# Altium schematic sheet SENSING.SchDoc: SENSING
size A3; DocumentNumber: 6; SheetNumber: 6; SheetTotal: 6
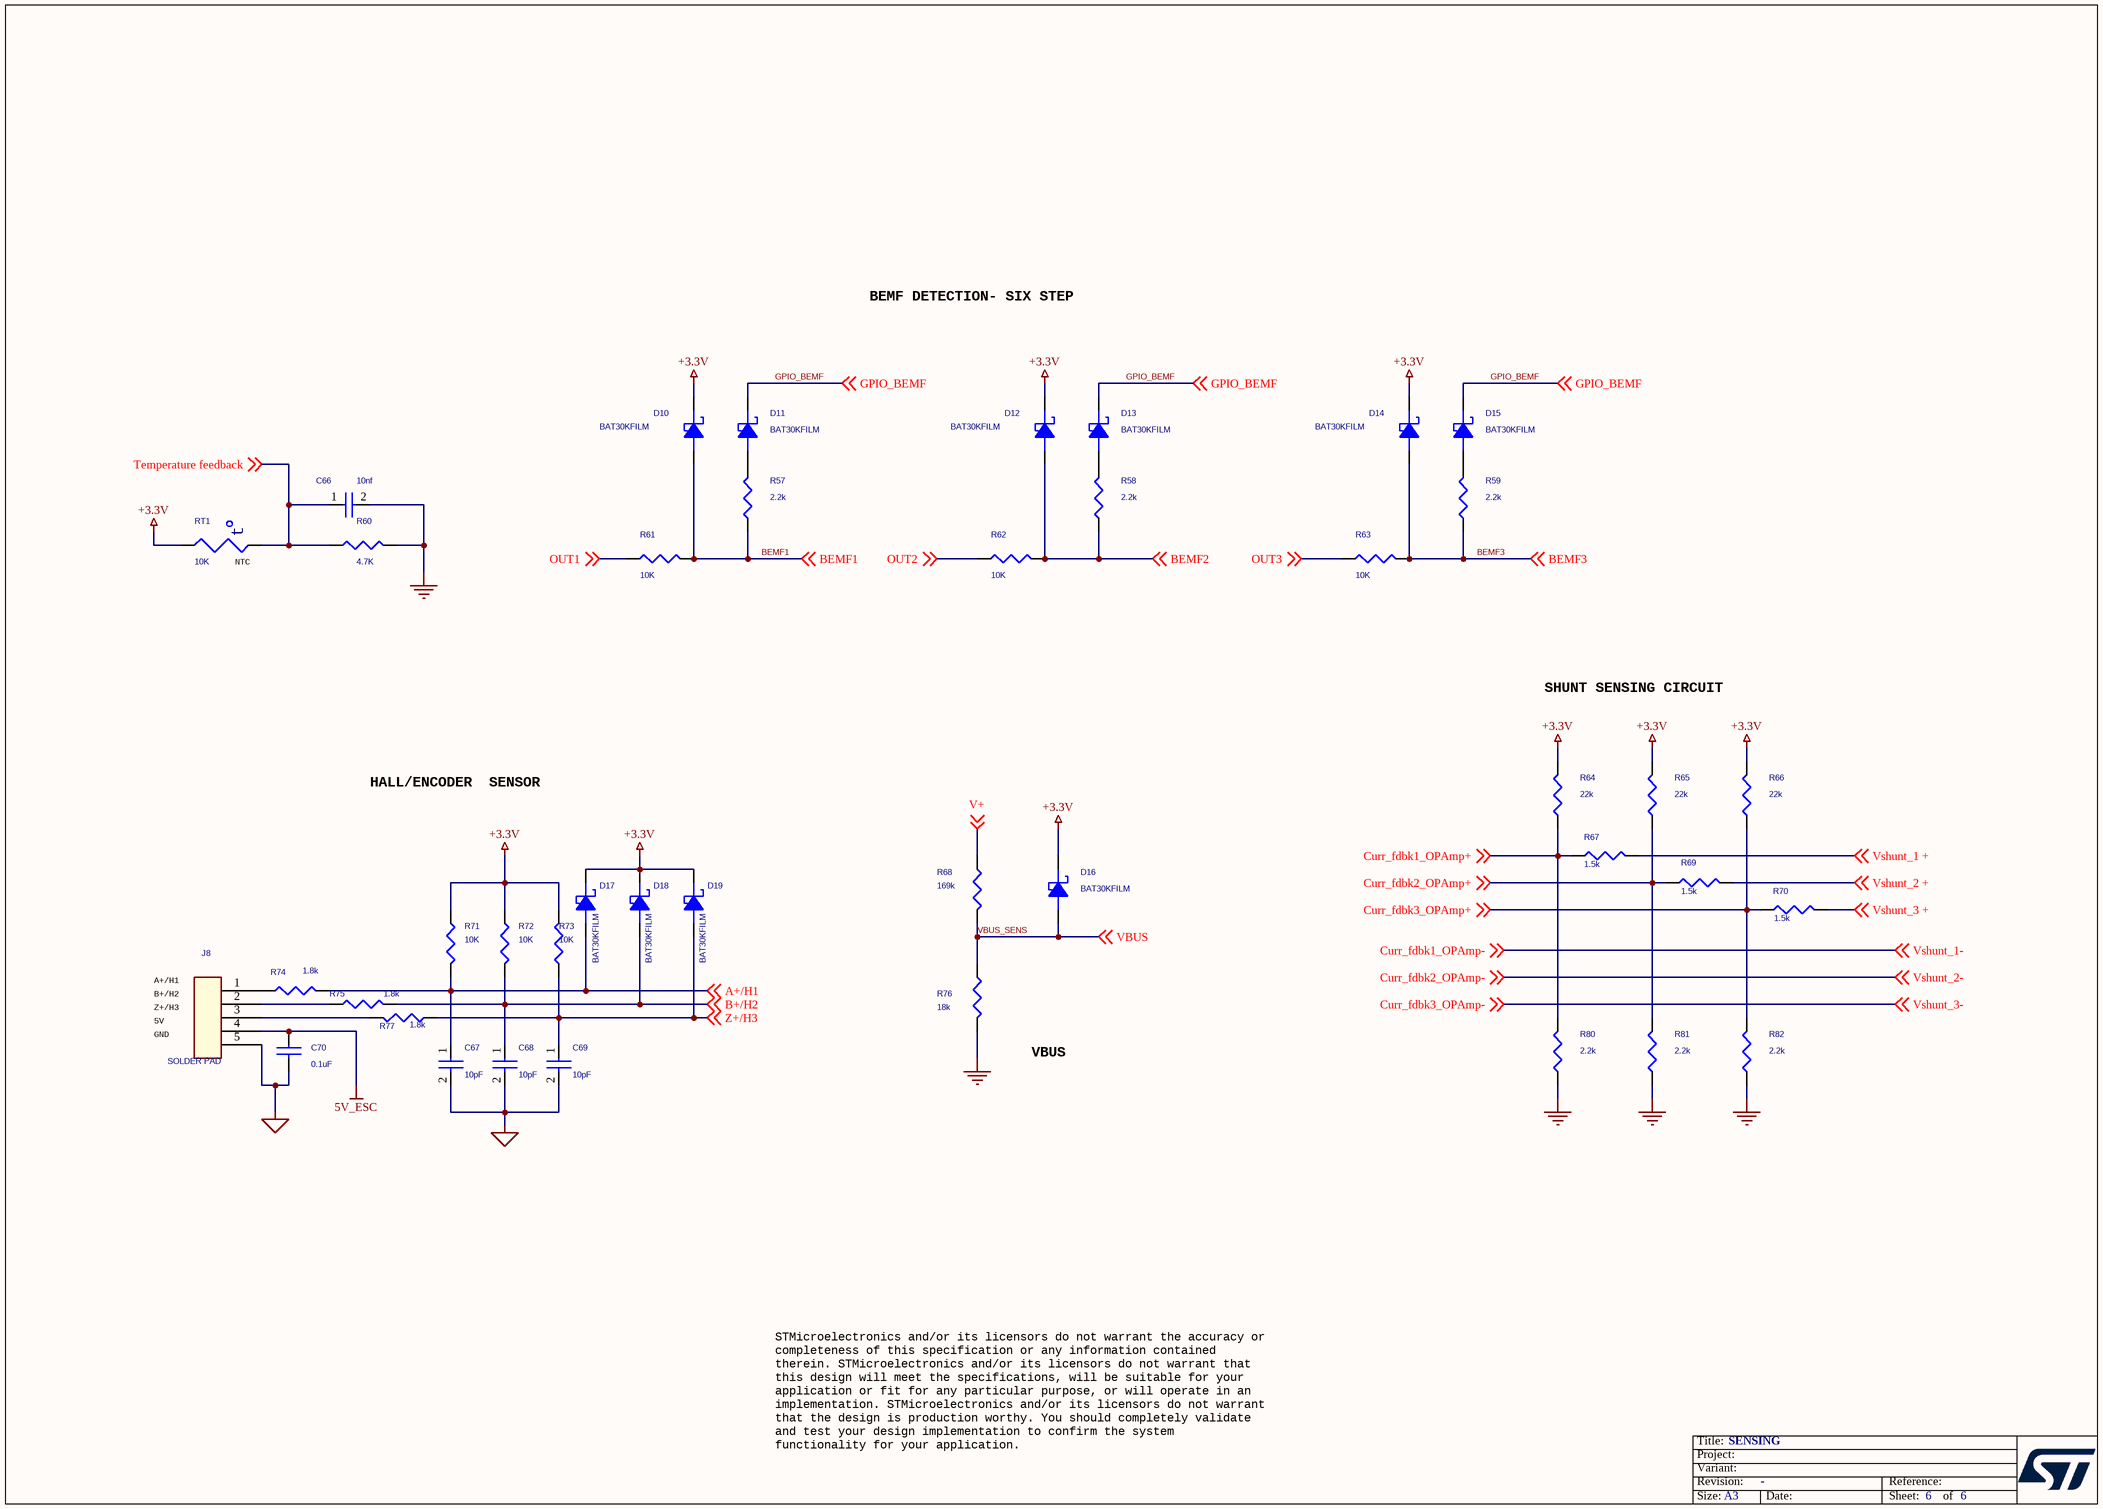
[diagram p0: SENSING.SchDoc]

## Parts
C66  10nf  [C_0402]
C67  10pF  [C_0402]
C68  10pF  [C_0402]
C69  10pF  [C_0402]
C70  0.1uF  [C_0402]
D10  BAT30KFILM  [sodfl160x80x65l30x30n]
D11  BAT30KFILM  [sodfl160x80x65l30x30n]
D12  BAT30KFILM  [sodfl160x80x65l30x30n]
D13  BAT30KFILM  [sodfl160x80x65l30x30n]
D14  BAT30KFILM  [sodfl160x80x65l30x30n]
D15  BAT30KFILM  [sodfl160x80x65l30x30n]
D16  BAT30KFILM  [sodfl160x80x65l30x30n]
D17  BAT30KFILM  [sodfl160x80x65l30x30n]
D18  BAT30KFILM  [sodfl160x80x65l30x30n]
D19  BAT30KFILM  [sodfl160x80x65l30x30n]
J8  SOLDER PAD  [SOLDER_PAD_5PIN_SMD]
R57  2.2k  [R_0402]
R58  2.2k  [R_0402]
R59  2.2k  [R_0402]
R60  4.7K  [R_0402]
R61  10K  [R_0603_HD]
R62  10K  [R_0603_HD]
R63  10K  [R_0603]
R64  22k  [r_0402]
R65  22k  [r_0402]
R66  22k  [r_0402]
R67  1.5k  [R_0402]
R68  169k  [R_0402]
R69  1.5k  [R_0402]
R70  1.5k  [R_0402]
R71  10K  [R_0402]
R72  10K  [R_0402]
R73  10K  [R_0402]
R74  1.8k  [R_0402]
R75  1.8k  [R_0402]
R76  18k  [R_0402]
R77  1.8k  [R_0402]
R80  2.2k  [R_0402]
R81  2.2k  [R_0402]
R82  2.2k  [R_0402]
RT1  10K  [R_0402]

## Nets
5V_ESC: C70.1 J8.4
+3.3V: D10.C D12.C D14.C D16.C D17.C D18.C D19.C R64.2 R65.2 R66.2 R71.1 R72.1 R73.2 RT1.1
GND: C66.2 R60.2 R76.2 R80.1 R81.1 R82.1
GND_SIGNAL: C67.2 C68.2 C69.2 C70.2 J8.5
A+/H1: C67.1 D17.A R71.2 R74.2 ; off-sheet A+/H1
B+/H2: C68.1 D18.A R72.2 R75.2 ; off-sheet B+/H2
BEMF1: D10.A R57.1 R61.2 ; off-sheet BEMF1
BEMF2: D12.A R58.1 R62.2 ; off-sheet BEMF2
BEMF3: D14.A R59.1 R63.2 ; off-sheet BEMF3
Curr_fdbk1_OPAmp+: R64.1 R67.1 R80.2 ; off-sheet Curr_fdbk1_OPAmp+
Curr_fdbk1_OPAmp-: off-sheet Curr_fdbk1_OPAmp-, off-sheet Vshunt_1-  [also labelled Vshunt_1-]
Curr_fdbk2_OPAmp+: R65.1 R69.1 R81.2 ; off-sheet Curr_fdbk2_OPAmp+
Curr_fdbk2_OPAmp-: off-sheet Curr_fdbk2_OPAmp-, off-sheet Vshunt_2-  [also labelled Vshunt_2-]
Curr_fdbk3_OPAmp+: R66.1 R70.1 R82.2 ; off-sheet Curr_fdbk3_OPAmp+
Curr_fdbk3_OPAmp-: off-sheet Curr_fdbk3_OPAmp-, off-sheet Vshunt_3-  [also labelled Vshunt_3-]
GPIO_BEMF: D11.C D13.C D15.C ; off-sheet GPIO_BEMF
OUT1: R61.1 ; off-sheet OUT1
OUT2: R62.1 ; off-sheet OUT2
OUT3: R63.1 ; off-sheet OUT3
Temperature feedback: C66.1 R60.1 RT1.2 ; off-sheet Temperature feedback
V+: R68.1 ; off-sheet V+
VBUS_SENS: D16.A R68.2 R76.1 ; off-sheet VBUS  [also labelled VBUS]
Vshunt_1 +: R67.2 ; off-sheet Vshunt_1 +
Vshunt_2 +: R69.2 ; off-sheet Vshunt_2 +
Vshunt_3 +: R70.2 ; off-sheet Vshunt_3 +
Z+/H3: C69.1 D19.A R73.1 R77.1 ; off-sheet Z+/H3
NetD11_A: D11.A R57.2
NetD13_A: D13.A R58.2
NetD15_A: D15.A R59.2
NetJ8_1: J8.1 R74.1
NetJ8_2: J8.2 R75.1
NetJ8_3: J8.3 R77.2

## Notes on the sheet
- BEMF DETECTION- SIX STEP
- (near RT1) NTC
- SHUNT SENSING CIRCUIT
- HALL/ENCODER  SENSOR
- (near J8) A+/H1
- 5V
- (near J8) Z+/H3
- (near J8) B+/H2
- GND
- VBUS
- STMicroelectronics and/or its licensors do not warrant the accuracy or
  completeness of this specification or any information contained
  therein. STMicroelectronics and/or its licensors do not warrant that
  this design will meet the specifications, will be suitable for your
  application or fit for any particular purpose, or will operate in an
  implementation. STMicroelectronics and/or its licensors do not warrant
  that the design is production worthy. You should completely validate
  and test your design implementation to confirm the system
  functionality for your application.

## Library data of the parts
C66 = CAP_Dup1: CAP CER 10000PF 10V X7R 0402; PART_NUMBER: CAP-00000003; Manufacturer: Wurth Electronics Inc.; Manufacturer PN: 885012205012; Dielectric Type: Capacitors; Tolerance: 10%; CLASS: DISCRETE
C67-C69 = CAP: CAP CER 10PF 10V C0G/NP0 0402; Manufacturer PN: 885012005007; Manufacturer: Wurth Electronics Inc.; PART_NUMBER: TMP-395; CLASS: DISCRETE; Tolerance: 5%; Temperature Coefficient: C0G, NP0; Dielectric Type: Capacitors
C70 = CAP_4: CAP CER 0.1UF 16V X7R 0402; Manufacturer PN: 885012205037; Manufacturer: Wurth Electronics Inc.; PART_NUMBER: CAP-00000053; CLASS: DISCRETE; Tolerance: 10%; Dielectric Type: Capacitors
D10 D17 D19 = DIODE_SCHOTTKY_0: DIODE SCHOTTKY 30V 300MA SOD523; Manufacturer: STMicroelectronics; PART_NUMBER: TMP-46; CLASS: DISCRETE; Rated Voltage: 530mV @ 300mA
D11-D16 D18 = DIODE_SCHOTTKY_0: DIODE SCHOTTKY 30V 300MA SOD523; PART_NUMBER: TMP-46; Manufacturer: STMicroelectronics; Rated Voltage: 530mV @ 300mA; CLASS: DISCRETE
J8 = CON5: SOLDER PADS
R57-R59 = RES: RES SMD 2.2K OHM 1% 1/16W 0402; Manufacturer PN: RC0402FR-072K2L; Manufacturer: Yageo; PART_NUMBER: TMP-444; CLASS: DISCRETE; Rated Power: 0.063W, 1/16W; Temperature Coefficient: 100ppm/C
R60 = RES: RES SMD 4.7K OHM 1% 1/16W 0402; PART_NUMBER: TMP-403; Manufacturer: TE Connectivity Passive Product; Manufacturer PN: CRG0402F4K7; Temperature Coefficient: 100ppm/C; Rated Power: 0.063W, 1/16W; CLASS: DISCRETE
R61 R62 = RES: RES SMD 10K OHM 1% 1/10W 0603; PART_NUMBER: RES-00000015; Manufacturer: Yageo; Manufacturer PN: RC0603FR-0710KL; Temperature Coefficient: 100ppm/C; Rated Power: 0.1W, 1/10W; CLASS: DISCRETE
R63 = RES: RES SMD 10K OHM 1% 1/10W 0603; PART_NUMBER: RES-00000015; Manufacturer: Yageo; Manufacturer PN: RC0603FR-0710KL; ALT_SYMBOLS: r_0603_hd; Temperature Coefficient: 100ppm/C; Rated Power: 0.1W, 1/10W; CLASS: DISCRETE
R64-R66 = RES: RES SMD 22K OHM 1% 1/10W 0402; PART_NUMBER: TMP-751; Manufacturer: Panasonic Electronic Components; Manufacturer PN: ERJ-2RKF2202X; Temperature Coefficient: 100ppm/C; Rated Power: 0.1W, 1/10W; CLASS: DISCRETE
R67 R69 R70 = RES: RES SMD 1.5K OHM 1% 1/16W 0402; PART_NUMBER: TMP-393; Manufacturer: Yageo; Manufacturer PN: RC0402FR-071K5L; Temperature Coefficient: 100ppm/C; Rated Power: 0.063W, 1/16W; CLASS: DISCRETE
R68 = RES: RES SMD 169K OHM 1% 1/16W 0402; PART_NUMBER: TMP-424; Manufacturer: Yageo; Manufacturer PN: RC0402FR-07169KL; Temperature Coefficient: 100ppm/C; Rated Power: 0.063W, 1/16W; CLASS: DISCRETE
R71 = RES: RES SMD 10K OHM 1% 1/16W 0402; PART_NUMBER: TMP-396; Manufacturer: Yageo; Manufacturer PN: RC0402FR-0710KL; Temperature Coefficient: 100ppm/C; Rated Power: 0.063W, 1/16W; CLASS: DISCRETE
R72 R73 = RES: RES SMD 10K OHM 1% 1/16W 0402; Manufacturer PN: RC0402FR-0710KL; Manufacturer: Yageo; PART_NUMBER: TMP-396; CLASS: DISCRETE; Rated Power: 0.063W, 1/16W; Temperature Coefficient: 100ppm/C
R74 = RES: RES SMD 1.8K OHM 1% 1/16W 0402; Manufacturer PN: RC0402FR-071K8L; Manufacturer: Yageo; PART_NUMBER: TMP-394; CLASS: DISCRETE; Rated Power: 0.063W, 1/16W; Temperature Coefficient: 100ppm/C
R75 R77 = RES: RES SMD 1.8K OHM 1% 1/16W 0402; PART_NUMBER: TMP-394; Manufacturer: Yageo; Manufacturer PN: RC0402FR-071K8L; Temperature Coefficient: 100ppm/C; Rated Power: 0.063W, 1/16W; CLASS: DISCRETE
R76 = RES: RES SMD 18K OHM 1% 1/16W 0402; PART_NUMBER: TMP-425; Manufacturer: Yageo; Manufacturer PN: RC0402FR-0718KL; Temperature Coefficient: 100ppm/C; Rated Power: 0.063W, 1/16W; CLASS: DISCRETE
R80-R82 = RES: RES SMD 2.2K OHM 1% 1/16W 0402; PART_NUMBER: TMP-444; Manufacturer: Yageo; Manufacturer PN: RC0402FR-072K2L; Temperature Coefficient: 100ppm/C; Rated Power: 0.063W, 1/16W; CLASS: DISCRETE
RT1 = NTC: NTC THERMISTOR 10K OHM 1% 0402; Manufacturer PN: NTCG103JF103FT1; Manufacturer: TDK Corporation; PART_NUMBER: TMP-423; CLASS: DISCRETE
